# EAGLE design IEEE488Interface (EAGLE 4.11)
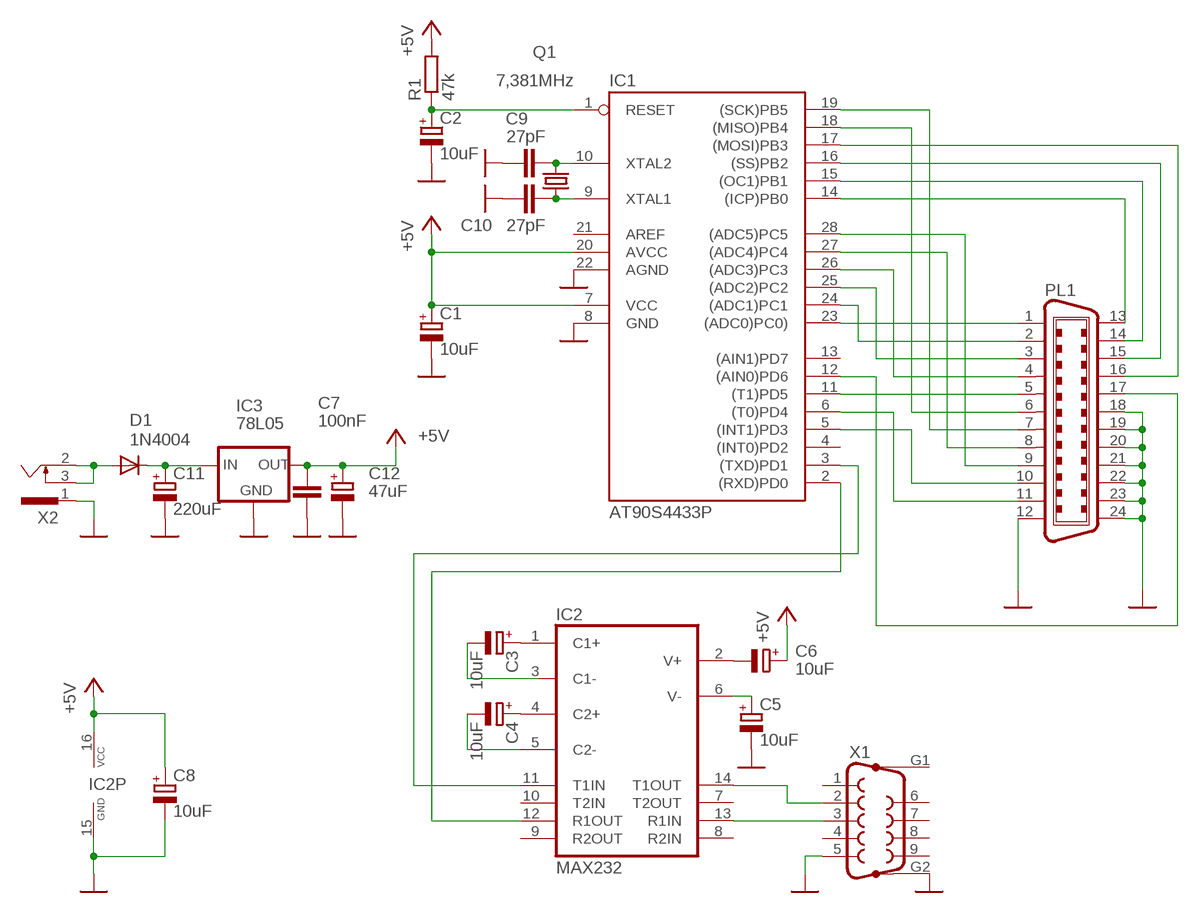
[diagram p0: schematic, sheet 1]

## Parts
C1  10uF  CPOL-EUB45181A  [B45181A]
C2  10uF  CPOL-EUB45181A  [B45181A]
C3  10uF  CPOL-EUB45181A  [B45181A]
C4  10uF  CPOL-EUB45181A  [B45181A]
C5  10uF  CPOL-EUB45181A  [B45181A]
C6  10uF  CPOL-EUB45181A  [B45181A]
C7  100nF  C-EU025-024X044  [C025-024X044]
C8  10uF  CPOL-EUB45181A  [B45181A]
C9  27pF  C-EU025-024X044  [C025-024X044]
C10  27pF  C-EU025-024X044  [C025-024X044]
C11  220uF  CPOL-EUB45181A  [B45181A]
C12  47uF  CPOL-EUB45181A  [B45181A]
D1  1N4004  [DO41-10]
IC1  AT90S4433P  [DIL28-3]
IC2  MAX232  [DIL16]
IC3  78L05  78LXX  [78LXX]
PL1  C24V  [24V]
Q1  7,381MHz  CRYTALHC49U-V  [HC49U-V]
R1  47k  R-EU_0204/7  [0204/7]
X1  F09HP  [F09HP]
X2  733989-55  [733989-5]

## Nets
+5V: C1.+ C6.+ C7.1 C8.+ C12.+ IC1.7(VCC) IC1.20(AVCC) IC2.16(VCC) IC3.OUT R1.2
GND: C1.- C2.- C5.- C7.2 C8.- C9.1 C10.1 C11.- C12.- IC1.8(GND) IC1.22(AGND) IC2.15(GND) IC3.GND PL1.12 PL1.18 PL1.19 PL1.20 PL1.21 PL1.22 PL1.23 PL1.24 X1.5 X1.G2 X2.1
N$1: IC1.23((ADC0)PC0)) PL1.1
N$2: IC1.24((ADC1)PC1) PL1.2
N$3: IC1.25((ADC2)PC2) PL1.3
N$4: IC1.26((ADC3)PC3) PL1.4
N$5: IC1.11((T1)PD5) PL1.5
N$6: IC1.18((MISO)PB4) PL1.6
N$7: IC1.19((SCK)PB5) PL1.7
N$8: IC1.27((ADC4)PC4) PL1.8
N$9: IC1.28((ADC5)PC5) PL1.9
N$10: IC1.5((INT1)PD3) PL1.10
N$11: IC1.6((T0)PD4) PL1.11
N$12: C6.- IC2.2(V+)
N$13: IC1.14((ICP)PB0) PL1.13
N$14: IC1.15((OC1)PB1) PL1.14
N$15: IC1.16((SS)PB2) PL1.15
N$16: IC1.17((MOSI)PB3) PL1.16
N$17: IC1.12((AIN0)PD6) PL1.17
N$18: C5.+ IC2.6(V-)
N$19: IC2.14(T1OUT) X1.2
N$20: IC2.13(R1IN) X1.3
N$21: C9.2 IC1.10(XTAL2) Q1.2
N$22: C3.- IC2.3(C1-)
N$23: C10.2 IC1.9(XTAL1) Q1.1
N$25: C2.+ IC1.1(RESET) R1.1
N$27: C3.+ IC2.1(C1+)
N$28: C4.+ IC2.4(C2+)
N$30: C11.+ D1.C IC3.IN
N$32: C4.- IC2.5(C2-)
N$33: D1.A X2.2 X2.3
N$34: IC1.2((RXD)PD0) IC2.12(R1OUT)
N$35: IC1.3((TXD)PD1) IC2.11(T1IN)
Unconnected: IC1.4((INT0)PD2) IC1.13((AIN1)PD7) IC2.7(T2OUT) IC2.8(R2IN) IC2.9(R2OUT) IC2.10(T2IN) X1.1 X1.4 X1.6 X1.7 X1.8 X1.9 X1.G1

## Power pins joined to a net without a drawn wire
AREF: IC1.21(AREF)

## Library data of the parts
C1-C6 C8 C11 C12 = rcl:CPOL-EU: POLARIZED CAPACITOR, European symbol
C7 C9 C10 = rcl:C-EU: CAPACITOR, European symbol
D1 = diode:1N4004: DIODE
IC1 = atmel:AT90S4433: MICROCONTROLLER 4 Kbytes FLASH 128 bytes SRAM 256 bytes EEPROM UART 6-channel 10 bit ADC
IC2 = maxim:MAX232: RS232 TRANSEIVER
IC3 = v-reg:78LXX: VOLTAGE REGULATOR
PL1 = con-amp-champ:C24V: CONNECTOR
Q1 = crystal:CRYTAL: CRYSTAL
R1 = rcl:R-EU_: RESISTOR, European symbol
X1 = con-subd:F09HP: SUB-D
X2 = con-conrad:733989-55: FEMALE PRINT CONNECTOR 1.1 mm, FUK HING Industries, distributor Conrad

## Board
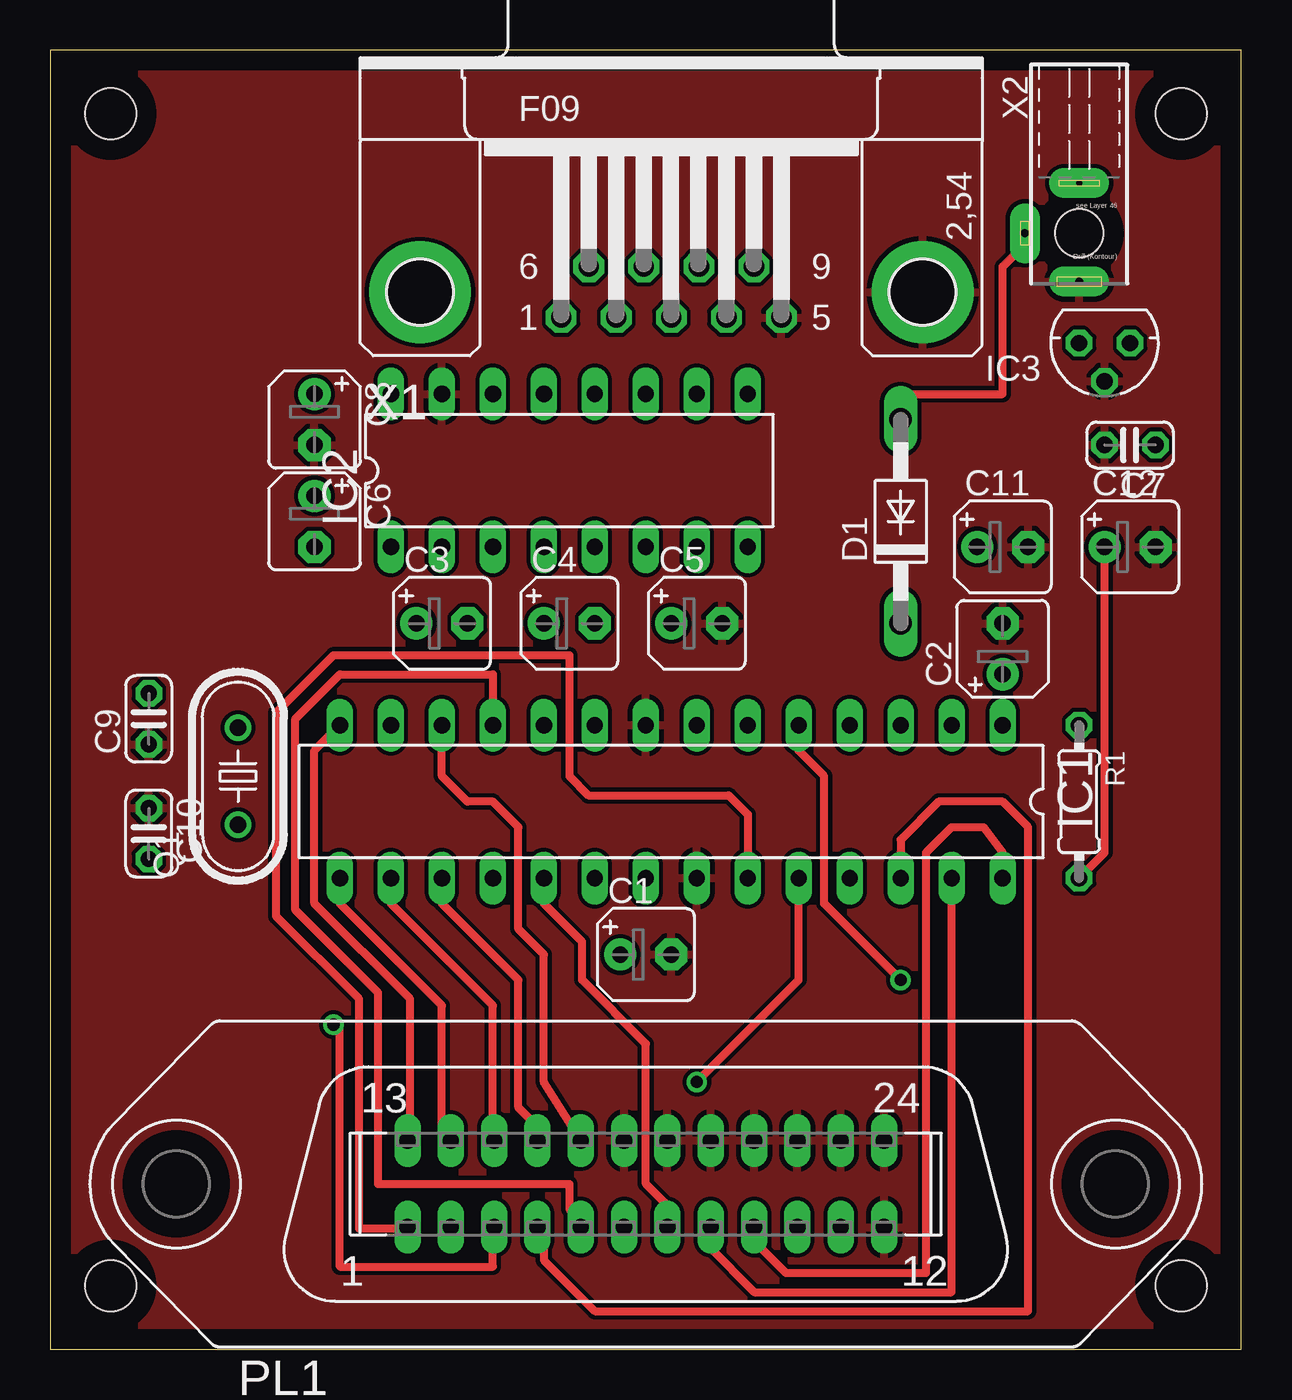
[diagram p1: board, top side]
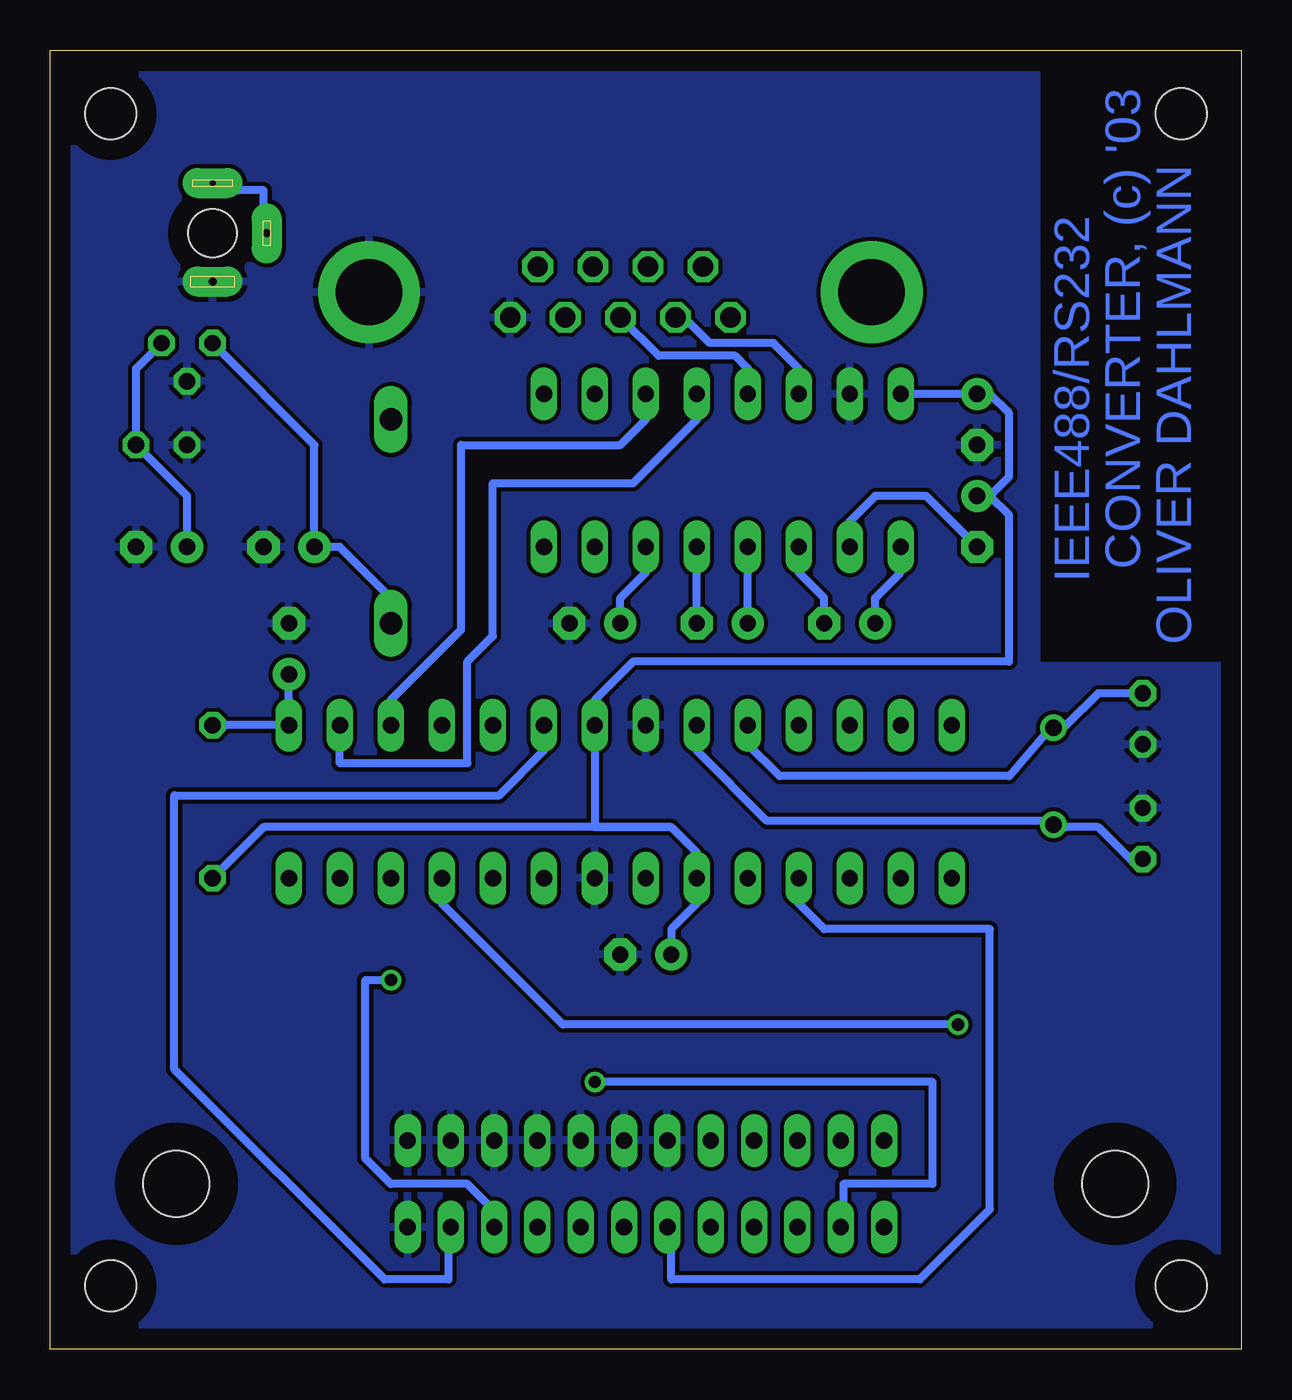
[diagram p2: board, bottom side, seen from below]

Size 59.36 x 64.76 mm. Coordinates in mm from the lower left corner, seen from the top.
Outline: 0,0 59.36,0 59.36,64.76 0,64.76 0,0
Copper layers (1*16): Top 0.035mm / dielectric 1.5mm / Bottom 0.035mm
Design rules "default": minimum track width 10mil, minimum drill 24mil, track to track 8mil, track to pad 8mil, pad to pad 8mil, via to via 8mil, smd to smd 8mil, copper to edge 40mil, drill to drill 8mil, minimum pad ring 10mil, minimum via ring 8mil, stop-mask expansion 4mil, vias tented up to drill 0mil, thermal gap 10mil
Holes 2.54 mm at 56.35,61.59 3.01,61.59 3.01,3.17 56.35,3.17
bRestrict: area 0.5,34.3 to 10,64.8

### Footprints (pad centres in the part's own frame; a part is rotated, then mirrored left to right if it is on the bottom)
B45181A = drill 0.813 pad 1.6 round: + -1.27,0 | drill 0.813 pad 1.6 octagon: - 1.27,0
C025-024X044 = drill 0.813 octagon: 1 -1.27,0; 2 1.27,0
DO41-10 = drill 1.118 long: A 5.08,0; C -5.08,0
DIL28-3 = drill 0.813 long: 1 -16.51,-3.81; 2 -13.97,-3.81; 3 -11.43,-3.81; 4 -8.89,-3.81; 5 -6.35,-3.81; 6 -3.81,-3.81; 7 -1.27,-3.81; 8 1.27,-3.81; 9 3.81,-3.81; 10 6.35,-3.81; 11 8.89,-3.81; 12 11.43,-3.81; 13 13.97,-3.81; 14 16.51,-3.81; 15 16.51,3.81; 16 13.97,3.81; 17 11.43,3.81; 18 8.89,3.81; 19 6.35,3.81; 20 3.81,3.81; 21 1.27,3.81; 22 -1.27,3.81; 23 -3.81,3.81; 24 -6.35,3.81; 25 -8.89,3.81; 26 -11.43,3.81; 27 -13.97,3.81; 28 -16.51,3.81
DIL16 = drill 0.813 long: 1 -8.89,-3.81; 2 -6.35,-3.81; 3 -3.81,-3.81; 4 -1.27,-3.81; 5 1.27,-3.81; 6 3.81,-3.81; 7 6.35,-3.81; 8 8.89,-3.81; 9 8.89,3.81; 10 6.35,3.81; 11 3.81,3.81; 12 1.27,3.81; 13 -1.27,3.81; 14 -3.81,3.81; 15 -6.35,3.81; 16 -8.89,3.81
78LXX = drill 0.813 octagon: GND 0,1.905; IN 1.27,0; OUT -1.27,0
24V = drill 0.813 long: 1 -11.874,-2.159; 2 -9.716,-2.159; 3 -7.556,-2.159; 4 -5.397,-2.159; 5 -3.239,-2.159; 6 -1.079,-2.159; 7 1.079,-2.159; 8 3.239,-2.159; 9 5.397,-2.159; 10 7.556,-2.159; 11 9.716,-2.159; 12 11.874,-2.159; 13 -11.874,2.159; 14 -9.716,2.159; 15 -7.556,2.159; 16 -5.397,2.159; 17 -3.239,2.159; 18 -1.079,2.159; 19 1.079,2.159; 20 3.239,2.159; 21 5.397,2.159; 22 7.556,2.159; 23 9.716,2.159; 24 11.874,2.159 | hole 3.302: -23.393,0; 23.393,0
HC49U-V = drill 0.813 round: 1 -2.413,0; 2 2.413,0
0204/7 = drill 0.813 octagon: 1 -3.81,0; 2 3.81,0
F09HP = drill 1.016 octagon: 1 -5.486,-1.27; 2 -2.743,-1.27; 3 0,-1.27; 4 2.743,-1.27; 5 5.486,-1.27; 6 -4.115,1.27; 7 -1.372,1.27; 8 1.372,1.27; 9 4.115,1.27 | drill 3.302 pad 5.08 round: G1 -12.522,0; G2 12.522,0
733989-5 = drill 0.4 pad 1.5 long: 1 0,5.82; 3 2.7,3.42 | drill 0.3 pad 1.5 long: 2 0,0.92 | hole 2.4: 0,3.42

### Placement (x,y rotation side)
C1  29.68,19.68 0 top
C2  47.46,34.92 90 top
C3  19.52,36.19 0 top
C4  25.87,36.19 0 top
C5  32.22,36.19 0 top
C6  13.17,41.27 270 top
C7  53.81,45.08 180 top
C8  13.17,46.35 270 top
C9  4.91,31.43 90 top
C10  4.91,25.71 270 top
C11  47.46,40 0 top
C12  53.81,40 0 top
D1  42.38,41.27 90 top
IC1  30.95,27.3 180 top
IC2  25.87,43.81 0 top
IC3  52.54,50.16 180 top
PL1  29.68,8.25 0 top
Q1  9.36,28.57 90 top
R1  51.27,27.3 270 top
X1  30.95,52.7 0 top
X2  51.27,59.05 180 top

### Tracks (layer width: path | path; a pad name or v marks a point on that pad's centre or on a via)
+5V  (via drill 0.61)
  Top 0.254: IC3.OUT | R1.2 | C7.1 | C12.+ | IC2.16 | C1.+
  Top 0.406: R1.2 52.54,24.76 C12.+
  Bottom 0.254: 12.54,42.54 C6.+ | C8.+ | IC2.16 | R1.2
  Bottom 0.406: C7.1 55.08,48.89 54.13,49.84 | 54.13,49.84 | 54.13,49.84 IC3.OUT | IC3.OUT | C7.1 52.54,42.54 C12.+ | C7.1 | C8.+ 12.54,47.62 11.58,46.67 11.58,45.71 11.58,43.49 12.54,42.54 11.58,41.59 11.58,34.28 30.31,34.28 32.22,32.38 IC1.7 32.22,29.84 32.22,26.03 28.41,26.03 | C8.+ | C8.+ 16.34,47.62 | 16.34,47.62 | 16.34,47.62 IC2.16 | C1.+ 28.41,20.95 27.14,22.22 IC1.20 27.14,24.76 28.41,26.03 | C1.+ | C1.+ | R1.2 48.73,26.03 28.41,26.03
  other vias: 52.54,40
GND
  pour Top: 0.15,64.77 59.21,64.77 59.21,0 0.15,0
  pour Bottom: 0.15,64.77 59.53,64.77 59.53,0 0.15,0
N$1
  Top 0.406: PL1.1 17.62,6.03 15.39,6.03 15.39,17.46 11.27,21.59 11.27,31.74 14.12,34.6 25.87,34.6 25.87,28.57 26.82,27.62 33.81,27.62 34.76,26.66 34.76,24.76 IC1.23
N$2  (via drill 0.61)
  Top 0.406: v32.22,13.33 37.3,18.41 37.3,22.22 IC1.24
  Bottom 0.406: v32.22,13.33 15.39,13.33 15.39,8.25 19.84,8.25 19.84,7.3 PL1.2
N$3  (via drill 0.61)
  Top 0.406: v14.12,16.19 14.44,16.19 14.44,4.12 22.06,4.12 22.06,5.71 PL1.3
  Bottom 0.406: v14.12,16.19 33.81,16.19 39.84,22.22 IC1.25
N$4
  Top 0.254: 44.28,27.3
  Top 0.406: PL1.4 24.6,5.71 24.6,4.44 27.14,1.9 48.73,1.9 48.73,26.03 47.46,27.3 44.28,27.3 42.38,25.39 42.38,24.76 IC1.26
N$5
  Top 0.406: PL1.5 25.87,6.98 25.87,8.25 16.34,8.25 16.34,17.77 12.22,21.9 12.22,31.43 14.44,33.65 22.06,33.65 IC1.11
N$6
  Bottom 0.406: PL1.6 28.41,5.71 28.41,3.49 16.03,3.49 12.54,6.98 12.54,20.95 20.79,20.95 22.06,22.22 IC1.18
N$7
  Top 0.406: PL1.7 30.95,6.98 29.68,8.25 29.68,15.24 26.51,18.41 26.51,20.31 24.6,22.22 IC1.19
N$8
  Top 0.254: 32.86,6.35 PL1.8
  Top 0.406: 32.86,6.35 32.86,5.08 35.08,2.85 44.92,2.85 44.92,22.22 IC1.27
N$9
  Top 0.254: 47.46,24.76 IC1.28
  Top 0.406: 47.46,24.76 46.51,26.03 44.92,26.03 43.65,24.76 43.65,3.81 36.67,3.81 35.08,5.39 PL1.9
N$10  (via drill 0.61)
  Top 0.406: v42.38,18.41 38.57,22.22 38.57,28.57 37.3,29.84 IC1.5
  Bottom 0.406: v42.38,18.41 43.65,18.41 43.65,9.52 42.38,8.25 38.57,8.25 37.3,6.98 PL1.10
N$11
  Bottom 0.406: PL1.11 39.52,5.71 39.52,3.49 42.7,3.49 53.17,13.97 53.17,27.62 36.98,27.62 34.76,29.84 IC1.6
N$12
  Bottom 0.254: C6.-
  Bottom 0.406: C6.- 15.71,42.54 18.25,42.54 19.52,41.27 IC2.2
N$13
  Top 0.406: PL1.13 17.93,11.42 17.93,17.46 13.17,22.22 13.17,29.84 IC1.14
N$14
  Top 0.406: PL1.14 19.52,10.79 19.52,17.14 14.44,22.22 IC1.15
N$15
  Top 0.406: PL1.15 22.06,10.79 22.06,17.14 16.98,22.22 IC1.16
N$16
  Top 0.406: PL1.16 24.6,10.79 23.33,12.06 23.33,18.41 19.52,22.22 IC1.17
N$17
  Top 0.406: PL1.17 24.6,13.33 24.6,19.68 23.33,20.95 23.33,26.03 22.06,27.3 20.79,27.3 19.52,28.57 IC1.12
N$18
  Top 0.254: C5.+
  Bottom 0.406: C5.+ 30.95,37.46 29.68,38.73 IC2.6 | C5.+ | C5.+ | C5.+
N$19
  Bottom 0.406: IC2.14 22.06,48.89 23.33,50.16 26.51,50.16 27.78,51.43 X1.2
N$20
  Bottom 0.406: IC2.13 24.6,48.89 25.23,49.52 29.05,49.52 X1.3
N$21
  Bottom 0.406: C9.2 7.14,32.7 8.73,31.11 Q1.2 9.68,30.79 11.58,28.57 23.01,28.57 24.6,30.16 IC1.10
N$22
  Top 0.254: C3.-
  Bottom 0.406: C3.- | C3.- | C3.- | C3.- 20.79,37.46 22.06,38.73 IC2.3
N$23
  Bottom 0.406: C10.2 5.55,24.44 7.14,26.03 8.73,26.03 Q1.1 9.99,26.35 23.65,26.35 27.14,29.84 IC1.9
N$25
  Top 0.254: C2.+ | R1.1 | IC1.1
  Bottom 0.406: 47.46,33.02 47.46,32.38 IC1.1 | 47.46,33.02 | 47.46,33.02 | 47.46,33.02 | 47.46,33.02 | 47.46,33.02 C2.+ | C2.+ | IC1.1 | IC1.1 | IC1.1 | IC1.1 | IC1.1 50.64,31.11 | 50.64,31.11 | 50.64,31.11 | 50.64,31.11 | 50.64,31.11 | 50.64,31.11 R1.1 | R1.1
N$27
  Top 0.254: C3.+
  Bottom 0.406: C3.+ 18.25,37.46 16.98,38.73 IC2.1 | C3.+ | C3.+ | C3.+
N$28
  Top 0.254: C4.+
  Bottom 0.406: C4.+ | C4.+ | C4.+ | C4.+ 24.6,38.73 IC2.4
N$30
  Bottom 0.254: C11.+
  Bottom 0.406: IC3.IN 46.19,45.08 C11.+ 44.92,40 42.38,37.46 D1.C
N$32
  Top 0.254: C4.-
  Bottom 0.406: C4.- | C4.- | C4.- | C4.- 27.14,38.73 IC2.5
N$33
  Top 0.406: 42.38,47.62 | 42.38,47.62 | 42.38,47.62 | 42.38,47.62 47.46,47.62 47.46,53.97 48.73,55.24 X2.3 | 42.38,47.62 D1.A
  Bottom 0.406: X2.3 48.73,56.51 48.73,57.78 50,57.78 X2.2
N$34
  Bottom 0.406: IC2.12 27.14,46.35 30.31,43.17 37.3,43.17 37.3,35.55 38.57,34.28 38.57,29.2 44.92,29.2 IC1.2
N$35
  Top 0.254: IC2.11
  Bottom 0.406: IC2.11 29.68,46.35 30.95,45.08 38.89,45.08 38.89,35.87 42.38,32.38 IC1.3 | IC2.11

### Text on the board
Bottom: CONVERTER, (c) '03 | OLIVER DAHLMANN | IEEE488/RS232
